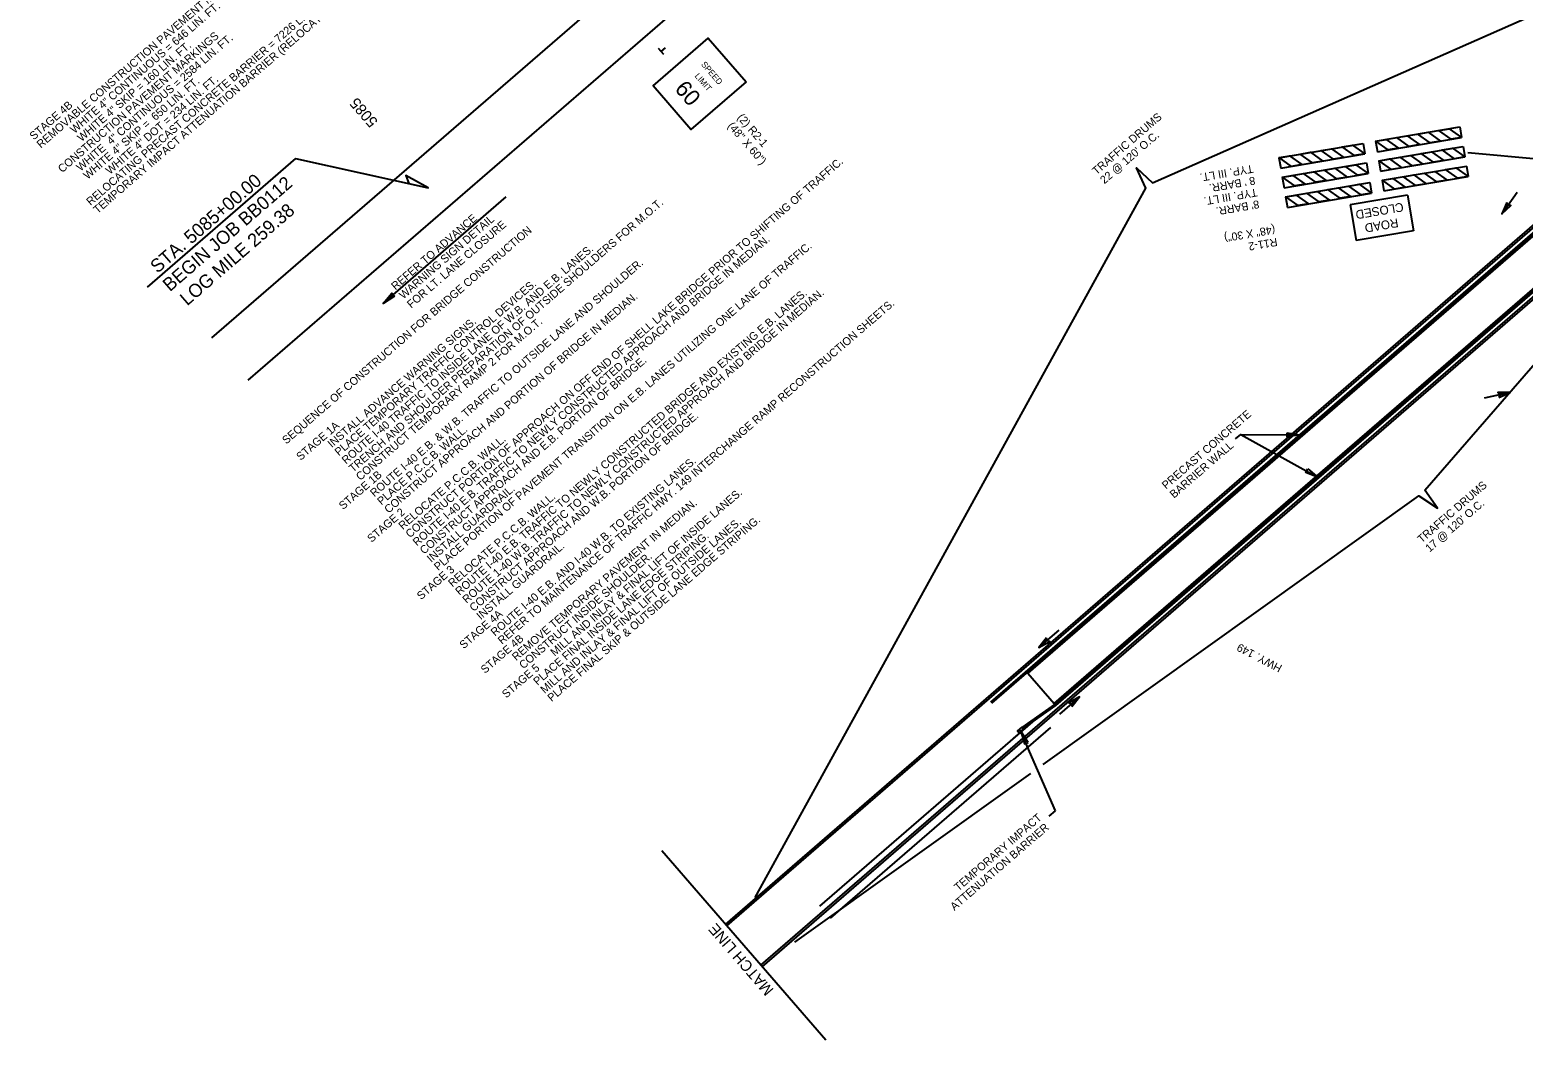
# Model space of a CAD drawing. Extents: x 259983 to 267998, y 211467 to 219827.
# Drawn here: x 264351 to 266591, y 211467 to 212982 of the extents above; entities that cross this region are included whole.
import ezdxf

# ---------------------------------------------------------------- set-up
doc = ezdxf.new("R2010")
doc.units = 0
for name, color, linetype in [('1', 7, 'Continuous'), ('Default', 7, 'Continuous'), ('Level 24', 7, 'Continuous'), ('Level 43', 7, 'Continuous'), ('Level 58', 7, 'Continuous'), ('Level 59', 7, 'Continuous'), ('R_MOT', 7, 'Continuous'), ('R_MOT STAGE 1', 7, 'Continuous'), ('R_MOT STAGE 2', 7, 'Continuous'), ('ROAD', 7, 'Continuous'), ('STATIONING1', 7, 'Continuous')]:
    doc.layers.add(name, color=color, linetype=linetype)

msp = doc.modelspace()

# ---------------------------------------------------------------- linework, layer by layer
at = {"layer": '1'}
for p, q in [((266167.6, 212375.1), (266283.7, 212310.8)), ((265889.6, 211810.4), (265836.6, 211931.7)), ((265880.4, 211802.4), (265889.6, 211810.4))]:
    msp.add_line(p, q, dxfattribs=at)
for points in [[(265439.2, 211680.6), (266025.4, 212744.6), (266011.1, 212775.1), (266035.2, 212752.4), (267342.6, 213329.5)], [(265871.3, 211879.9), (266434.6, 212283), (266462.7, 212264.5), (266443.7, 212291.7), (266947.2, 212871.1)], [(266160, 212368.5), (266167.6, 212375.1), (266256.9, 212374.5)], [(265498.7, 211613.3), (265852.7, 211866.6)]]:
    msp.add_lwpolyline(points, dxfattribs=at)
for points in [[(264898.2, 212582.5), (264881.3, 212571.8), (264894.3, 212587)], [(266237.2, 212377.7), (266256.9, 212374.5), (266237.1, 212371.7)], [(266268.2, 212323.4), (266283.7, 212310.8), (266265.1, 212318.2)], [(265848.6, 211913.2), (265837.9, 211930.2), (265843.1, 211910.8)]]:
    msp.add_lwpolyline(points, close=True, dxfattribs=at)
at = {"layer": 'Level 24'}
for points in [[(264749.8, 212789), (264527.2, 212596.2)], [(264749.8, 212789), (264948.6, 212745.3)]]:
    msp.add_lwpolyline(points, dxfattribs=at)
at = {"layer": 'Level 43'}
for points in [[(266559.3, 212706.1), (266582.1, 212738.6)], [(266571.8, 212438), (266533, 212429.6)], [(265865, 212055.4), (265895.1, 212081.4)], [(265925.7, 211981.4), (265895.6, 211955.4)]]:
    msp.add_lwpolyline(points, dxfattribs=at)
at = {"layer": 'Level 58'}
for points in [[(266566.6, 212723), (266559.3, 212706.1), (266572.7, 212718.7), (266567.9, 212718.4)], [(266555, 212430.5), (266571.8, 212438), (266553.4, 212437.9), (266557.1, 212434.8)], [(265876.2, 212070.1), (265865, 212055.4), (265881.1, 212064.4), (265876.4, 212065.3)], [(265914.5, 211966.8), (265925.7, 211981.4), (265909.6, 211972.4), (265914.3, 211971.5)]]:
    msp.add_lwpolyline(points, close=True, dxfattribs=at)
at = {"layer": 'Level 59'}
msp.add_lwpolyline([(264919.8, 212751.6), (264948.6, 212745.3), (264915.3, 212763.4)], close=True, dxfattribs=at)
at = {"layer": 'R_MOT'}
for p, q in [((265302.3, 212945.1), (265294.3, 212954.3)), ((265298.3, 212949.7), (265304.7, 212955.3)), ((266369.9, 212815), (266496.1, 212836.5)), ((266496.1, 212836.5), (266498.8, 212820.7)), ((266224.9, 212790.3), (266351.1, 212811.8)), ((266351.1, 212811.8), (266353.8, 212796)), ((266369.9, 212815), (266372.6, 212799.2)), ((266372.6, 212799.2), (266498.8, 212820.7)), ((266224.9, 212790.3), (266227.6, 212774.5)), ((266227.6, 212774.5), (266353.8, 212796)), ((266374.8, 212785.7), (266501.1, 212807.2)), ((266374.8, 212785.7), (266377.5, 212769.9)), ((266377.5, 212769.9), (266503.8, 212791.4)), ((266501.1, 212807.2), (266503.8, 212791.4)), ((266501.1, 212807.2), (266503.8, 212791.4)), ((266229.9, 212761), (266356.1, 212782.5)), ((266232.6, 212745.2), (266358.8, 212766.7)), ((266356.1, 212782.5), (266358.8, 212766.7)), ((266356.1, 212782.5), (266358.8, 212766.7)), ((266379.8, 212756.4), (266506.1, 212777.8)), ((266506, 212777.8), (266506.1, 212777.7)), ((266506.1, 212777.8), (266508.8, 212762)), ((266229.9, 212761), (266232.6, 212745.2)), ((266234.9, 212731.7), (266361.1, 212753.2)), ((266361, 212753.1), (266361.1, 212753)), ((266361.1, 212753.2), (266363.8, 212737.3)), ((266379.8, 212756.4), (266382.5, 212740.5)), ((266382.5, 212740.5), (266508.8, 212762)), ((266234.9, 212731.7), (266237.6, 212715.8)), ((266237.6, 212715.8), (266363.8, 212737.3)), ((266417.6, 212734.2), (266331.9, 212719.6)), ((266331.9, 212719.6), (266341, 212666.1)), ((266417.6, 212734.2), (266426.7, 212680.7)), ((266426.7, 212680.7), (266341, 212666.1))]:
    msp.add_line(p, q, dxfattribs=at)
for points in [[(265425.9, 212904), (265343, 212832.4), (265286.2, 212898.1), (265369, 212969.7)], [(266498.8, 212820.7), (266483.3, 212818.1), (266464.8, 212831.1), (266480.3, 212833.8)], [(266353.8, 212796), (266338.3, 212793.4), (266319.9, 212806.5), (266335.3, 212809.1)], [(266404.2, 212804.6), (266388.6, 212802), (266370.2, 212815), (266385.7, 212817.7)], [(266435.7, 212809.9), (266420.2, 212807.3), (266401.7, 212820.4), (266417.2, 212823)], [(266467.3, 212815.3), (266451.7, 212812.7), (266433.3, 212825.8), (266448.8, 212828.4)], [(266259.2, 212779.9), (266243.7, 212777.3), (266225.2, 212790.4), (266240.7, 212793)], [(266290.7, 212785.3), (266275.2, 212782.7), (266256.8, 212795.7), (266272.2, 212798.4)], [(266322.3, 212790.6), (266306.7, 212788), (266288.3, 212801.1), (266303.8, 212803.7)], [(266409.1, 212775.3), (266393.6, 212772.7), (266375.2, 212785.8), (266390.6, 212788.4)], [(266440.7, 212780.6), (266425.2, 212778), (266406.7, 212791.1), (266422.2, 212793.8)], [(266472.2, 212786), (266456.7, 212783.4), (266438.3, 212796.5), (266453.7, 212799.1)], [(266503.8, 212791.4), (266488.3, 212788.8), (266469.8, 212801.9), (266485.3, 212804.5)], [(266264.2, 212750.6), (266248.6, 212748), (266230.2, 212761.1), (266245.7, 212763.7)], [(266295.7, 212756), (266280.2, 212753.4), (266261.7, 212766.5), (266277.2, 212769.1)], [(266327.3, 212761.3), (266311.7, 212758.7), (266293.3, 212771.8), (266308.8, 212774.5)], [(266358.8, 212766.7), (266343.3, 212764.1), (266324.8, 212777.2), (266340.3, 212779.8)], [(266445.7, 212751.3), (266430.2, 212748.7), (266411.7, 212761.7), (266427.2, 212764.4)], [(266477.2, 212756.6), (266461.7, 212754), (266443.3, 212767.1), (266458.7, 212769.7)], [(266508.8, 212762), (266493.3, 212759.4), (266474.8, 212772.5), (266490.3, 212775.1)], [(266332.3, 212732), (266316.7, 212729.4), (266298.3, 212742.4), (266313.8, 212745.1)], [(266363.8, 212737.3), (266348.3, 212734.7), (266329.8, 212747.8), (266345.3, 212750.4)], [(266414.1, 212745.9), (266398.6, 212743.3), (266380.2, 212756.4), (266395.6, 212759)], [(266269.2, 212721.2), (266253.6, 212718.6), (266235.2, 212731.7), (266250.7, 212734.3)], [(266300.7, 212726.6), (266285.2, 212724), (266266.7, 212737.1), (266282.2, 212739.7)]]:
    msp.add_lwpolyline(points, close=True, dxfattribs=at)
at = {"layer": 'R_MOT STAGE 1'}
for p, q in [((264624.1, 212519.9), (266458.3, 214107.8)), ((264679, 212456.4), (266513.2, 214044.3)), ((265394.8, 211640.2), (267378.2, 213357.2)), ((265396.8, 211637.9), (267380.1, 213354.9)), ((267265, 213248.7), (265792.3, 211973.7)), ((267266.4, 213247.2), (265793.6, 211972.2)), ((267267.7, 213245.6), (265967.2, 212119.8)), ((265447.8, 211578.9), (266985.1, 212909.8)), ((265449.8, 211576.7), (266987.1, 212907.5)), ((265889, 211970.1), (266935.4, 212876)), ((265890.3, 211968.6), (266936.7, 212874.5)), ((266227.9, 212266.2), (266836.7, 212793.2)), ((266629.8, 212693.5), (266586.5, 212656)), ((266586.5, 212656), (266530.5, 212607.5)), ((266530.5, 212607.5), (266196.1, 212317.9)), ((266196.1, 212317.9), (266188.6, 212311.5)), ((266188.6, 212311.5), (265848.4, 212017)), ((265887.7, 211971.6), (266227.9, 212266.2)), ((266227.9, 212266.2), (266227.9, 212266.2)), ((265848.4, 212017), (265848.4, 212017)), ((265848.4, 212017), (265848.4, 212017)), ((265848.4, 212017), (265848.4, 212017)), ((265848.4, 212017), (265887.7, 211971.6)), ((265840, 211935.5), (265889, 211970.1)), ((265841.1, 211933.9), (265890.1, 211968.5)), ((265889, 211970.1), (265890.1, 211968.5)), ((265889, 211970.1), (265890.3, 211968.6)), ((265536.5, 211667.6), (265867, 211953.7)), ((265552.2, 211649.4), (265882.7, 211935.6)), ((265827.5, 211919.5), (265865.6, 211952.5)), ((265841.1, 211933.9), (265840, 211935.5)), ((265545.2, 211466.5), (265299.5, 211750.3))]:
    msp.add_line(p, q, dxfattribs=at)
msp.add_lwpolyline([(265839.4, 211935.9), (265833, 211930.5), (265835.5, 211927.6), (265841.8, 211933.1)], close=True, dxfattribs=at)
msp.add_arc((266530.5, 212607.5), 0.0119, 301.4252, 322.9315, dxfattribs=at)
at = {"layer": 'R_MOT STAGE 2'}
for p, q in [((266508.1, 212798.2), (266617.8, 212788.2)), ((264881.3, 212571.8), (265065.7, 212731.4))]:
    msp.add_line(p, q, dxfattribs=at)

# ---------------------------------------------------------------- texts
at = {"layer": '1'}
for s, rotation, p in [('TRAFFIC DRUMS', 40.9073, (265951.3, 212763.8)), ("22 @ 120' O.C.", 40.9073, (265963.1, 212750.2)), ('REFER TO ADVANCE', 40.8733, (264899.8, 212591)), ('WARNING SIGN DETAIL', 40.8733, (264911.6, 212577.4)), ('FOR LT. LANE CLOSURE', 40.8733, (264923.4, 212563.8)), ('PRECAST CONCRETE', 40.8833, (266055.7, 212292.3)), ('BARRIER WALL', 40.8833, (266067.5, 212278.7)), ('TRAFFIC DRUMS', 40.9261, (266439.1, 212211.5)), ("17 @ 120' O.C.", 40.9261, (266450.9, 212197.9)), ('HWY. 149', 152.3599, (266230.7, 212028.3)), ('TEMPORARY IMPACT', 40.8933, (265744.2, 211689.3)), ('ATTENUATION BARRIER', 40.8933, (265738.2, 211660.2))]:
    msp.add_text(s, height=12, rotation=rotation, dxfattribs=at).set_placement(p)
at = {"layer": 'Default'}
for s, p in [('REMOVABLE CONSTRUCTION PAVEMENT MARKINGS', (264367.9, 212803.9)), ('TEMPORARY IMPACT ATTENUATION BARRIER (RELOCATION) = 2 EACH', (264453, 212705.6)), ('RELOCATING PRECAST CONCRETE BARRIER = 7226 LIN. FT.', (264442.4, 212717.9)), (' WHITE 4" CONTINUOUS = 646 LIN. FT.', (264414.9, 212823)), ('CONSTRUCTION PAVEMENT MARKINGS', (264399.9, 212767)), ('     WHITE  4" CONTINUOUS = 2584 LIN. FT.', (264410.5, 212754.7)), (' WHITE 4" SKIP = 160 LIN. FT.', (264425.5, 212810.7)), ('     WHITE 4" SKIP =  650 LIN. FT.', (264421.1, 212742.5)), (' WHITE 4" DOT = 234 LIN. FT.', (264468.1, 212761.6)), ('STAGE 4B', (264357.3, 212816.2))]:
    msp.add_text(s, height=12, rotation=40.8833, dxfattribs=at).set_placement(p)
at = {"layer": 'Level 24'}
for s, p in [('STA. 5085+00.00', (264542.8, 212616)), ('BEGIN JOB BB0112', (264561.4, 212588.5)), ('LOG MILE 259.38', (264587.3, 212567.3))]:
    msp.add_text(s, height=20, rotation=40.8833, dxfattribs=at).set_placement(p)
at = {"layer": 'R_MOT'}
for s, height, rotation, p in [('SPEED', 9.05, 310.8555, (265357.6, 212929.9)), ('60', 24.26, 310.8555, (265317.4, 212892.9)), ('LIMIT', 9.05, 310.8555, (265347.9, 212912.4)), ('(2) R2-1', 12.13, 310.8555, (265411.5, 212850.1)), ('(48" X 60")', 12.129, 310.8555, (265397.1, 212837.5)), ('TYP. III LT.', 12, 189.6559, (266185.3, 212779.8)), ('TYP. III LT.', 12, 189.6559, (266191.3, 212744.3)), ("8 ' BARR.", 12, 189.6559, (266188.3, 212762.1)), ("8' BARR.", 12, 189.6559, (266194.3, 212726.6)), ('CLOSED', 13.22, 189.6559, (266410.6, 212723.1)), ('ROAD', 13.15, 189.6559, (266402.8, 212699.4)), ('(48" X 30")', 12, 189.6559, (266218.3, 212688.5)), ('R11-2', 12, 189.6559, (266221.5, 212670))]:
    msp.add_text(s, height=height, rotation=rotation, dxfattribs=at).set_placement(p)
at = {"layer": 'ROAD'}
for s, p in [('CONSTRUCT PORTION OF APPROACH ON OFF END OF SHELL LAKE BRIDGE PRIOR TO SHIFTING OF TRAFFIC.', (264921.3, 212219.3)), ('TRENCH AND SHOULDER PREPARATION OF OUTSIDE SHOULDERS FOR M.O.T.', (264836.2, 212317.6)), ('SEQUENCE OF CONSTRUCTION FOR BRIDGE CONSTRUCTION', (264736.1, 212359.9)), ('ROUTE I-40 TRAFFIC TO INSIDE LANE OF W.B. AND E.B. LANES.', (264825.6, 212329.9)), ('ROUTE I-40 E.B. TRAFFIC TO NEWLY CONSTRUCTED APPROACH AND BRIDGE IN MEDIAN.', (264932, 212207)), ('PLACE PORTION OF PAVEMENT TRANSITION ON E.B. LANES UTILIZING ONE LANE OF TRAFFIC.', (264963.9, 212170.1)), ('ROUTE I-40 E.B. & W.B. TRAFFIC TO OUTSIDE LANE AND SHOULDER.', (264868.1, 212280.7)), ('PLACE TEMPORARY TRAFFIC CONTROL DEVICES.', (264814.9, 212342.2)), ('CONSTRUCT APPROACH AND PORTION OF BRIDGE IN MEDIAN.', (264889.4, 212256.1)), ('ROUTE I-40 E.B. TRAFFIC TO NEWLY CONSTRUCTED BRIDGE AND EXISTING E.B. LANES.', (264995.8, 212133.2)), ('ROUTE 1-40 W.B. TRAFFIC TO NEWLY CONSTRUCTED APPROACH AND BRIDGE IN MEDIAN.', (265006.5, 212121)), ('REFER TO MAINTENANCE OF TRAFFIC HWY. 149 INTERCHANGE RAMP RECONSTRUCTION SHEETS.', (265059.6, 212059.5)), ('INSTALL ADVANCE WARNING SIGNS.', (264804.3, 212354.5)), ('CONSTRUCT TEMPORARY RAMP 2 FOR M.O.T.', (264846.9, 212305.3)), ('CONSTRUCT APPROACH AND E.B. PORTION OF BRIDGE.', (264942.6, 212194.7)), ('CONSTRUCT APPROACH AND W.B. PORTION OF BRIDGE.', (265017.1, 212108.7)), ('STAGE 1A', (264757.4, 212335.3)), ('PLACE P.C.C.B. WALL.', (264878.8, 212268.4)), ('RELOCATE P.C.C.B. WALL.', (264910.7, 212231.6)), ('ROUTE I-40 E.B. AND I-40 W.B. TO EXISTING LANES.', (265049, 212071.8)), ('STAGE 1B', (264821.2, 212261.6)), ('INSTALL GUARDRAIL.', (264953.3, 212182.4)), ('RELOCATE P.C.C.B. WALL.', (264985.2, 212145.5)), ('REMOVE TEMPORARY PAVEMENT IN MEDIAN.', (265080.9, 212034.9)), ('MILL AND INLAY & FINAL LIFT OF INSIDE LANES.', (265138.5, 212041.8)), ('STAGE 2', (264863.8, 212212.4)), ('PLACE FINAL SKIP & OUTSIDE LANE EDGE STRIPING.', (265134.1, 211973.5)), ('PLACE FINAL INSIDE LANE EDGE STRIPING.', (265112.8, 211998.1)), ('MILL AND INLAY & FINAL LIFT OF OUTSIDE LANES.', (265123.5, 211985.8)), ('INSTALL GUARDRAIL.', (265027.7, 212096.4)), ('CONSTRUCT INSIDE SHOULDER.', (265091.6, 212022.6)), ('STAGE 3', (264938.2, 212126.4)), ('STAGE 4A', (265002.1, 212052.7)), ('STAGE 4B', (265034, 212015.8)), ('STAGE 5', (265065.9, 211978.9))]:
    msp.add_text(s, height=12, rotation=40.8833, dxfattribs=at).set_placement(p)
at = {"layer": 'STATIONING1'}
for s, p in [('5085', (264874.3, 212844.8)), ('MATCH LINE', (265467.9, 211542.2))]:
    msp.add_text(s, height=16.5, rotation=130.8833, dxfattribs=at).set_placement(p)

doc.saveas('drawing.dxf')
